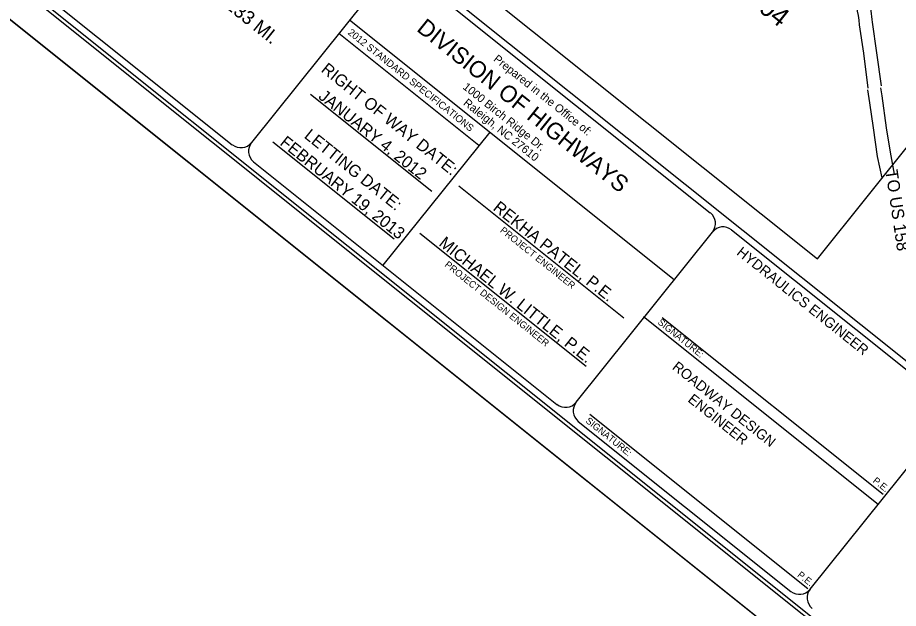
# Model space of a CAD drawing. Extents: x 1732765 to 1738218, y 913652 to 917906.
# Drawn here: x 1733974 to 1735266, y 914187 to 915055 of the extents above; entities that cross this region are included whole.
import ezdxf

# ---------------------------------------------------------------- set-up
doc = ezdxf.new("R2010")
doc.units = 0
for name, color, linetype in [('Old_Level_23', 7, 'Continuous'), ('Old_Level_3', 7, 'Continuous'), ('Old_Level_38', 7, 'Continuous'), ('Prop DSN Text', 7, 'Continuous'), ('Prop Rip Rap Related Quantities Text', 7, 'Continuous'), ('Sheet Cutting Line CELL', 7, 'Continuous'), ('Sheet Data Field CELL', 7, 'Continuous'), ('Sheet Plot Border Inside CELL', 7, 'Continuous'), ('Sheet Title CELL', 7, 'Continuous')]:
    doc.layers.add(name, color=color, linetype=linetype)

msp = doc.modelspace()

# ---------------------------------------------------------------- linework, layer by layer
at = {"layer": 'Old_Level_3'}
for points in [[(1735209.1, 915044.3), (1735215, 915002.5), (1735221.8, 914951.3)], [(1735228.1, 915047.9), (1735234.5, 915002.8), (1735240.9, 914954.5)], [(1735260.6, 914824.7), (1735254.7, 914857), (1735249.1, 914892.7), (1735242.4, 914939.7), (1735240.8, 914951.5)], [(1735242.5, 914819.2), (1735236, 914850.6), (1735229.7, 914892.9), (1735224.3, 914929.5), (1735221.6, 914948.5)]]:
    msp.add_lwpolyline(points, dxfattribs=at)
for points in [[(1734856.1, 915608.7), (1734893.5, 915576.7), (1734932.1, 915545.3), (1734970.6, 915512.8), (1735003.9, 915482.3), (1735037.8, 915446.3), (1735070.3, 915406.1), (1735094.7, 915371.1), (1735119.9, 915328.1), (1735140.3, 915288.8), (1735161.8, 915240.4), (1735177, 915198.7), (1735191.5, 915143.6), (1735200.8, 915097.7), (1735209.1, 915044.3)], [(1735194.5, 915207.7), (1735207.4, 915160.4), (1735216.9, 915116.7), (1735223.4, 915081), (1735228.1, 915047.9)]]:
    msp.add_spline(points, degree=3, dxfattribs=at)
at = {"layer": 'Prop Rip Rap Related Quantities Text'}
msp.add_lwpolyline([(1733985, 915648.7), (1733976.3, 915637.9), (1735147.5, 914700.6), (1735803.5, 915520.4)], dxfattribs=at)
at = {"layer": 'Sheet Cutting Line CELL'}
msp.add_line((1732765.3, 916010.8), (1735394.8, 913906.4), dxfattribs=at)
at = {"layer": 'Sheet Data Field CELL'}
msp.add_lwpolyline([(1736769.5, 915624), (1734139.9, 917728.5), (1732765.3, 916010.8), (1735394.8, 913906.4)], close=True, dxfattribs=at)
at = {"layer": 'Sheet Plot Border Inside CELL'}
msp.add_lwpolyline([(1732813.6, 916029.6), (1735415.9, 913947), (1736734.4, 915594.6), (1734132.1, 917677.2)], close=True, dxfattribs=at)
at = {"layer": 'Sheet Title CELL'}
for p, q in [((1733396.2, 916056.6), (1735613.6, 914282.1)), ((1734517.4, 915121), (1734317.4, 914871.1)), ((1734545.5, 915124.1), (1734990.5, 914767.9)), ((1734937.7, 914669.9), (1734461.4, 915051.1)), ((1734650.9, 914866.7), (1734445.5, 915031.2)), ((1734581.8, 914799.5), (1734404.1, 914941.7)), ((1734591.7, 914914.1), (1734591.7, 914914.1)), ((1734666.9, 914886.7), (1734510.3, 914691.1)), ((1734526.6, 914729.4), (1734349, 914871.6)), ((1734492.9, 914870.6), (1734492.9, 914870.6)), ((1734621.4, 914807.8), (1734863.7, 914613.9)), ((1734564.6, 914738), (1734808.6, 914542.7)), ((1734793.7, 914489.9), (1734993.6, 914739.8)), ((1735021.7, 914742.9), (1735333.7, 914493.3)), ((1734892.3, 914616), (1735236.9, 914340.3)), ((1734920.1, 914614.3), (1735244.1, 914354.9)), ((1734813.7, 914472.5), (1735133.4, 914216.6)), ((1735136.9, 914215.3), (1735336.8, 914465.2))]:
    msp.add_line(p, q, dxfattribs=at)
for points in [[(1733072.9, 915828.7), (1735383.9, 913979.1)], [(1733695.9, 915342.8), (1734289.3, 914868)], [(1734320.5, 914843), (1734765.6, 914486.8)], [(1734796.8, 914461.8), (1735108.7, 914212.2)]]:
    msp.add_lwpolyline(points, dxfattribs=at)
for centre, start, end in [((1734301.9, 914883.7), 231.3297, 321.3297), ((1734333.1, 914858.7), 141.3297, 231.3297), ((1734978.1, 914752.4), 321.3297, 51.3297), ((1735009.3, 914727.4), 51.3297, 141.3297), ((1734778.1, 914502.5), 231.3297, 321.3297), ((1734809.4, 914477.5), 141.3297, 231.3297), ((1735121.3, 914227.9), 231.3297, 321.3297), ((1735152.5, 914202.9), 141.3297, 231.3297)]:
    msp.add_arc(centre, 20, start, end, dxfattribs=at)

# ---------------------------------------------------------------- texts
at = {"layer": 'Old_Level_23'}
msp.add_text('END TIP PROJECT B-4804', height=28, rotation=321.3297, dxfattribs=at).set_placement((1734729.8, 915329.3))
at = {"layer": 'Old_Level_38'}
msp.add_text('= 0.133 MI.', height=20, rotation=321.3297, dxfattribs=at).set_placement((1734242.3, 915098.6))
at = {"layer": 'Prop DSN Text'}
msp.add_text('TO US 158', height=18, rotation=278.3862, dxfattribs=at).set_placement((1735247.3, 914830.1))
at = {"layer": 'Sheet Data Field CELL'}
for s, p in [('JANUARY 4, 2012 ', (1734414.4, 914936.8)), ('FEBRUARY 19, 2013', (1734357.9, 914868.8)), ('REKHA PATEL, P.E.', (1734670.5, 914773.1)), ('MICHAEL W. LITTLE, P.E.', (1734591.1, 914721))]:
    msp.add_text(s, height=17.5, rotation=321.3297, dxfattribs=at).set_placement(p)
at = {"layer": 'Sheet Title CELL'}
for s, height, p in [('DIVISION OF HIGHWAYS', 24.374, (1734558.4, 915036.1)), ('2012 STANDARD SPECIFICATIONS', 10.4, (1734457.9, 915031.1)), ('Prepared in the Office of:', 11.999, (1734671.4, 914992)), ('RIGHT OF WAY DATE: ', 17.5, (1734418.3, 914976.2)), ('1000 Birch Ridge Dr.', 12, (1734626.4, 914951.1)), ('Raleigh, NC 27610', 12, (1734627.2, 914927.5)), ('LETTING DATE:', 17.5, (1734393.5, 914879.1)), ('PROJECT ENGINEER', 9.999, (1734681.3, 914740.7)), (' HYDRAULICS ENGINEER', 15, (1735023.7, 914711.2)), ('PROJECT DESIGN ENGINEER', 9.999, (1734600, 914690.3)), ('SIGNATURE:', 10, (1734912.5, 914605.7)), ('ROADWAY DESIGN', 14.999, (1734933.5, 914539.5)), ('ENGINEER', 15, (1734956.4, 914491.8)), ('SIGNATURE:', 10, (1734806.7, 914461)), ('P.E.', 10, (1735228, 914373.1)), ('P.E.', 10, (1735117.3, 914234.8))]:
    msp.add_text(s, height=height, rotation=321.3297, dxfattribs=at).set_placement(p)

doc.saveas('drawing.dxf')
